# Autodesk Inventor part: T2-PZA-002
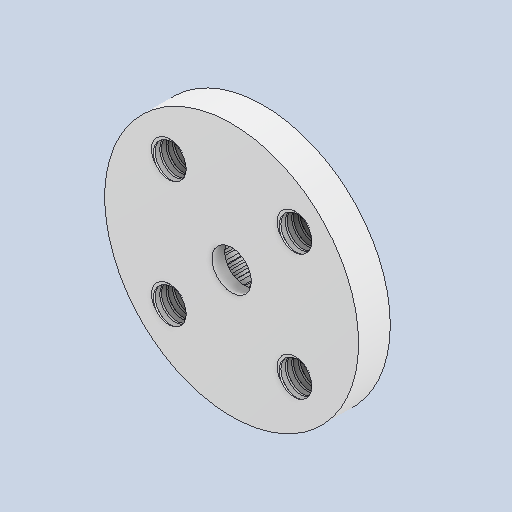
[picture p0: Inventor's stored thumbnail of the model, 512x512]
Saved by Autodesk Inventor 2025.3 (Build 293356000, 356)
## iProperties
Created: 2026-10
Part Number: T2-PZA-002
Material: Acier
Document SubType Name: Modeling
Designer: Luis MuÃ±oz
Density: 7.85 g/cm^3
Appearance: Valor por defecto
Project: TESIS 2 - Plataforma mecatrÃ³nica preventiva desacoplada
Description: Acople del eje de salida del servomotor
Material_Fabricacion: PLA
Author: Luis M
Title: Acople del eje de salida del servomotor
Revision Number: 00
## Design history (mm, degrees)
feature "Corps1"
node "Sólido1"
